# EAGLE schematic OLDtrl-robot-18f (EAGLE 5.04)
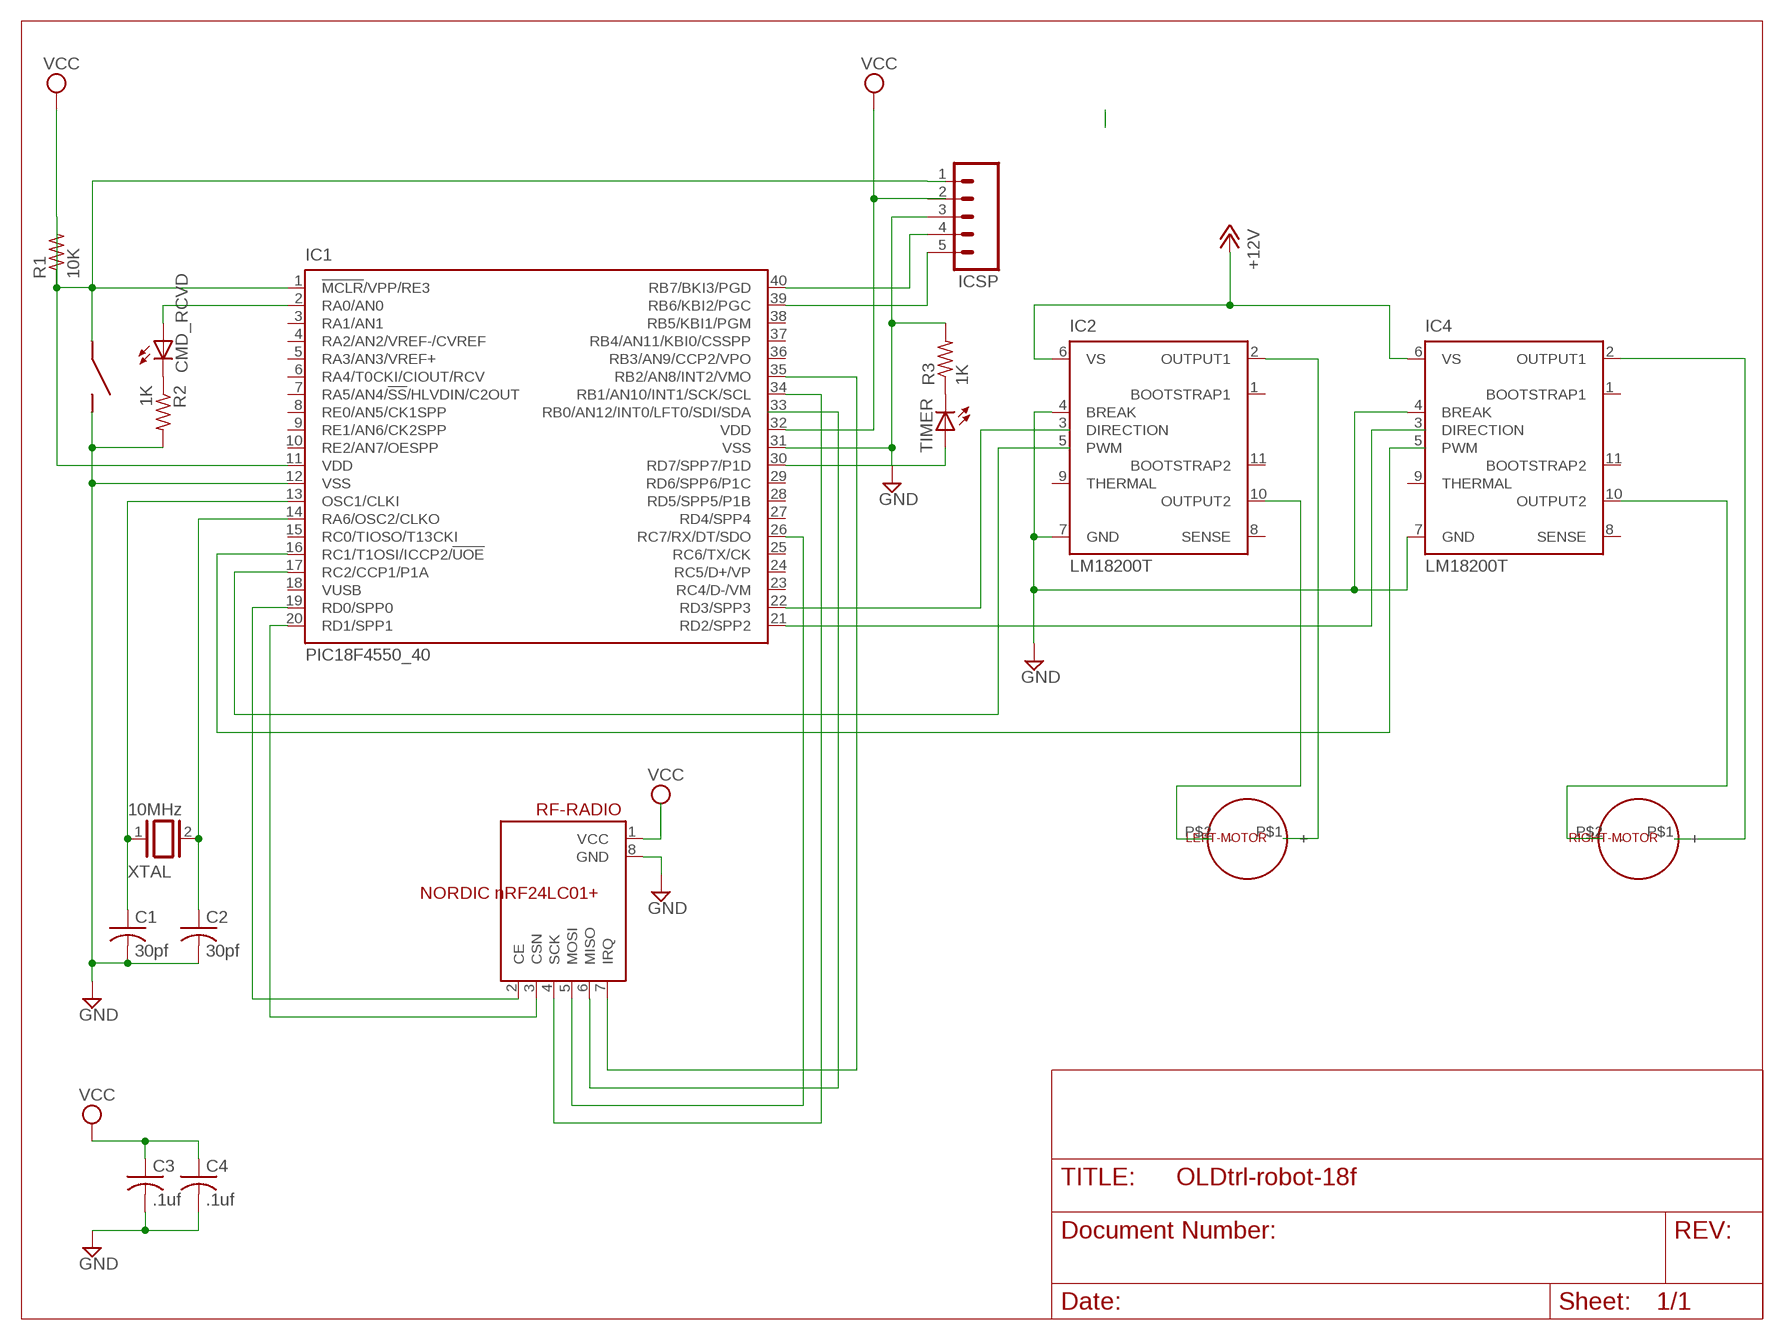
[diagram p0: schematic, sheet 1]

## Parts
C1  30pf  C-US102-043X133  [C102-043X133]
C2  30pf  C-US102-043X133  [C102-043X133]
C3  .1uf  C-US102-043X133  [C102-043X133]
C4  .1uf  C-US102-043X133  [C102-043X133]
CMD_RCVD  LEDCHIPLED_0603  [CHIPLED_0603]
IC1  PIC18F4550_40  [DIL40]
IC2  LM18200T  [TO-220-11]
IC4  LM18200T  [TO-220-11]
ICSP  M05  [05P]
LEFT-MOTOR  DC-MOTOR  [DC-MOTOR]
R1  10K  R-US_0617/22  [0617/22]
R2  1K  R-US_0617/22  [0617/22]
R3  1K  R-US_0617/22  [0617/22]
RESET  PUSH-BUTTON-SWITCH  [2SIL]
RF-RADIO  NORDIC nRF24LC01+  NORDIC-BREAKOUT  [8SIL]
RIGHT-MOTOR  DC-MOTOR  [DC-MOTOR]
TIMER  LEDCHIPLED_0603  [CHIPLED_0603]
XTAL  10MHz  XTAL  [Q]

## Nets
+12V: IC2.6(VS) IC4.6(VS)
GND: C1.2 C2.2 C3.2 C4.2 IC1.12(VSS) IC1.31(VSS) IC2.4(BREAK) IC2.7(GND) IC4.4(BREAK) IC4.7(GND) ICSP.3 R2.2 R3.2 RESET.NO RF-RADIO.8(GND)
L-MOTOR: IC2.10(OUTPUT2) LEFT-MOTOR.P$2(-)
N$1: CMD_RCVD.C R2.1
N$2: CMD_RCVD.A IC1.2(RA0/AN0)
N$3: IC2.2(OUTPUT1) LEFT-MOTOR.P$1(+)
N$4: IC4.2(OUTPUT1) RIGHT-MOTOR.P$1(+)
N$5: IC1.39(RB6/KBI2/PGC) ICSP.5
N$6: IC1.40(RB7/BKI3/PGD) ICSP.4
N$8: IC4.10(OUTPUT2) RIGHT-MOTOR.P$2(-)
N$9: C1.1 IC1.13(OSC1/CLKI) XTAL.1
N$10: C2.1 IC1.14(RA6/OSC2/CLKO) XTAL.2
N$11: IC1.19(RD0/SPP0) RF-RADIO.2(CE)
N$12: IC1.16(RC1/T1OSI/ICCP2/!UOE)
N$14: IC1.22(RD3/SPP3)
N$15: IC1.21(RD2/SPP2)
N$16: RF-RADIO.6(MISO)
N$17: IC1.20(RD1/SPP1) RF-RADIO.3(CSN)
N$18: R3.1 TIMER.C
N$19: IC1.30(RD7/SPP7/P1D) TIMER.A
N$20: IC1.26(RC7/RX/DT/SDO) RF-RADIO.5(MOSI)
N$21: IC1.34(RB1/AN10/INT1/SCK/SCL) RF-RADIO.4(SCK)
N$22: IC1.35(RB2/AN8/INT2/VMO) RF-RADIO.7(IRQ)
VCC: C3.1 C4.1 IC1.1(!MCLR!/VPP/RE3) IC1.11(VDD) IC1.32(VDD) ICSP.1 ICSP.2 R1.1 R1.2 RESET.COM RF-RADIO.1(VCC)
Unconnected: IC1.3(RA1/AN1) IC1.4(RA2/AN2/VREF-/CVREF) IC1.5(RA3/AN3/VREF+) IC1.6(RA4/T0CKI/CIOUT/RCV) IC1.7(RA5/AN4/!SS!/HLVDIN/C2OUT) IC1.8(RE0/AN5/CK1SPP) IC1.9(RE1/AN6/CK2SPP) IC1.10(RE2/AN7/OESPP) IC1.15(RC0/TIOSO/T13CKI) IC1.17(RC2/CCP1/P1A) IC1.18(VUSB) IC1.23(RC4/D-/VM) IC1.24(RC5/D+/VP) IC1.25(RC6/TX/CK) IC1.27(RD4/SPP4) IC1.28(RD5/SPP5/P1B) IC1.29(RD6/SPP6/P1C) IC1.33(RB0/AN12/INT0/LFT0/SDI/SDA) IC1.36(RB3/AN9/CCP2/VPO) IC1.37(RB4/AN11/KBI0/CSSPP) IC1.38(RB5/KBI1/PGM) IC2.1(BOOTSTRAP1) IC2.3(DIRECTION) IC2.5(PWM) IC2.8(SENSE) IC2.9(THERMAL) IC2.11(BOOTSTRAP2) IC4.1(BOOTSTRAP1) IC4.3(DIRECTION) IC4.5(PWM) IC4.8(SENSE) IC4.9(THERMAL) IC4.11(BOOTSTRAP2)

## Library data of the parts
C1-C4 = rcl:C-US: CAPACITOR, American symbol
CMD_RCVD TIMER = led:LED: LED
IC1 = microchip:PIC18F4*_40: USB Microcontrollers with nanoWatt Technology High-Performance, Enhanced Flash, 28/40/44-Pin, Source: http://ww1.microchip.com/downloads/en/devicedoc/39632c.pdf
IC2 IC4 = national-semiconductor:LM18200T: 3A, 55V H-Bridge Motor Control SourcE: http://cache.national.com/ds/LM/LMD18200.pdf
ICSP = con-amp-quick:M05: AMP QUICK CONNECTOR
LEFT-MOTOR RIGHT-MOTOR = trl:DC-MOTOR: DC Motor
R1-R3 = resistor:R-US_: RESISTOR, American symbol
RESET = trl:PUSH-BUTTON-SWITCH
RF-RADIO = trl:NORDIC-BREAKOUT: Spark Fun Electronic's Nordic Semiconductor nRF24L01 with chip antenna
XTAL = special:XTAL: CRYSTAL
